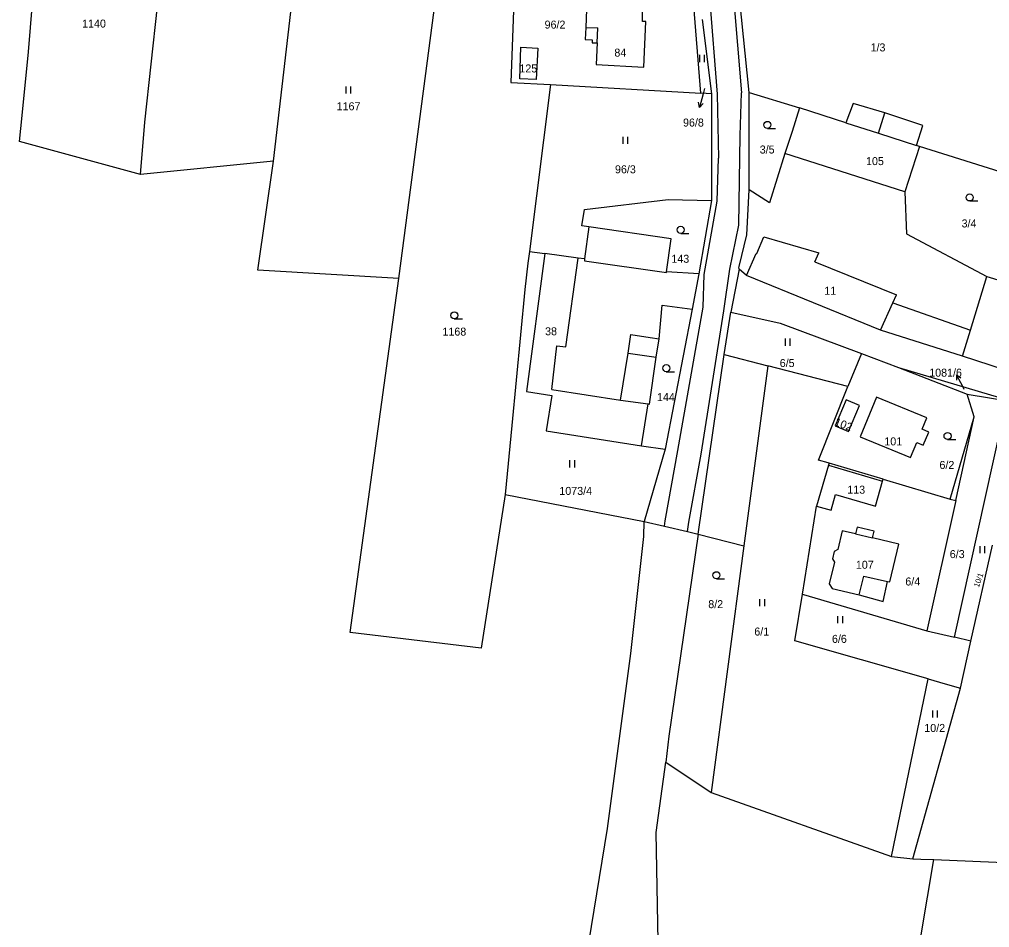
# Model space of a CAD drawing. Extents: x -746176 to -739709, y -1128407 to -1124482.
# Drawn here: x -742307.4 to -742101.3, y -1126433.2 to -1126240.2 of the extents above; entities that cross this region are included whole.
import ezdxf

# ---------------------------------------------------------------- set-up
doc = ezdxf.new("R2010")
doc.units = 0
for name, color, linetype in [('Hranice parcel', 7, 'Continuous'), ('Parcelní čísla', 7, 'Continuous'), ('Pop  PČ popisy', 7, 'Continuous'), ('Vnitřní kresba', 7, 'Continuous'), ('Značky kultur', 7, 'Continuous')]:
    doc.layers.add(name, color=color, linetype=linetype)

msp = doc.modelspace()

# ---------------------------------------------------------------- linework, layer by layer
at = {"layer": 'Hranice parcel'}
for p, q in [((-742152.42, -1126255.73), (-742159.24, -1126187.68)), ((-742253.45, -1126270.36), (-742246.8, -1126213.59)), ((-742226.78, -1126295.24), (-742218.41, -1126231.43)), ((-742162.64, -1126255.9), (-742164.34, -1126234.95)), ((-742162.38, -1126240.19), (-742160.39, -1126256.03)), ((-742194.57, -1126254.06), (-742199.05, -1126289.55)), ((-742194.57, -1126254.06), (-742162.64, -1126255.9)), ((-742160.39, -1126256.03), (-742162.64, -1126255.9)), ((-742160.39, -1126256.03), (-742160.39, -1126278.66)), ((-742152.42, -1126255.73), (-742141.7, -1126259.03)), ((-742152.35, -1126276.44), (-742152.42, -1126255.73)), ((-742116.22, -1126267.19), (-742119.31, -1126276.84)), ((-742090.65, -1126275.25), (-742116.22, -1126267.19)), ((-742253.45, -1126270.36), (-742281.72, -1126273.18)), ((-742119.31, -1126276.84), (-742144.79, -1126268.68)), ((-742160.39, -1126278.66), (-742163.05, -1126294.31)), ((-742199.05, -1126289.55), (-742195.79, -1126289.99)), ((-742163.05, -1126294.31), (-742164.48, -1126301.76)), ((-742154.48, -1126293.27), (-742156.3, -1126302.44)), ((-742164.48, -1126301.76), (-742170.24, -1126331.56)), ((-742157.68, -1126311.4), (-742156.3, -1126302.44)), ((-742163.24, -1126349.58), (-742157.68, -1126311.4)), ((-742157.68, -1126311.4), (-742148.42, -1126313.8)), ((-742128.49, -1126311.19), (-742131.46, -1126318.2)), ((-742128.49, -1126311.19), (-742120.66, -1126314.22)), ((-742131.46, -1126318.2), (-742148.42, -1126313.8)), ((-742120.66, -1126314.22), (-742106.07, -1126319.87)), ((-742120.66, -1126314.22), (-742095.86, -1126321.55)), ((-742137.67, -1126333.86), (-742131.46, -1126318.2)), ((-742106.07, -1126319.87), (-742095.86, -1126321.55)), ((-742175.26, -1126330.82), (-742170.24, -1126331.56)), ((-742170.24, -1126331.56), (-742174.68, -1126346.91)), ((-742135.58, -1126334.46), (-742137.67, -1126333.86)), ((-742135.39, -1126334.52), (-742135.58, -1126334.46)), ((-742123.93, -1126337.94), (-742135.39, -1126334.52)), ((-742204.22, -1126341.19), (-742174.68, -1126346.91)), ((-742108.51, -1126342.48), (-742114.63, -1126370.19)), ((-742141.07, -1126362.36), (-742138.05, -1126343.65)), ((-742105.28, -1126372.36), (-742100.72, -1126351.93)), ((-742141.07, -1126362.36), (-742140.82, -1126362.44)), ((-742140.82, -1126362.44), (-742114.63, -1126370.19)), ((-742114.63, -1126370.19), (-742108.8, -1126371.54)), ((-742105.28, -1126372.36), (-742108.8, -1126371.54)), ((-742107.51, -1126382.37), (-742105.28, -1126372.36)), ((-742122.15, -1126418.14), (-742114.39, -1126380.39)), ((-742114.39, -1126380.39), (-742110.73, -1126381.44)), ((-742110.73, -1126381.44), (-742107.51, -1126382.37)), ((-742117.61, -1126418.59), (-742107.51, -1126382.37)), ((-742170.12, -1126398.06), (-742160.44, -1126404.55)), ((-742160.44, -1126404.55), (-742122.15, -1126418.14)), ((-742122.15, -1126418.14), (-742117.61, -1126418.59)), ((-742113.18, -1126418.78), (-742091.83, -1126419.68))]:
    msp.add_line(p, q, dxfattribs=at)
for points in [[(-742281.72, -1126273.18), (-742307.41, -1126266.17), (-742306.81, -1126260.62), (-742305.51, -1126247.12), (-742302.59, -1126211.7)], [(-742281.72, -1126273.18), (-742280.8, -1126262.02), (-742276.72, -1126225.02), (-742275.09, -1126215.95)], [(-742202.22, -1126232.53), (-742203.02, -1126253.58), (-742194.57, -1126254.06)], [(-742185.73, -1126244.55), (-742185.76, -1126245.16), (-742184.7, -1126245.2), (-742184.9, -1126249.82), (-742174.78, -1126250.38), (-742174.35, -1126240.63), (-742175.05, -1126240.62), (-742175.01, -1126238.6), (-742186.93, -1126238.09), (-742187.1, -1126241.89), (-742187.21, -1126244.49), (-742185.73, -1126244.55)], [(-742200.86, -1126246.11), (-742197.3, -1126246.29), (-742197.64, -1126252.97), (-742201.12, -1126252.84), (-742200.86, -1126246.11)], [(-742116.22, -1126267.19), (-742116.82, -1126267), (-742115.46, -1126262.77), (-742123.54, -1126260.09), (-742130.31, -1126258.08), (-742131.85, -1126262.18), (-742141.7, -1126259.03)], [(-742141.7, -1126259.03), (-742143.26, -1126264), (-742144.79, -1126268.68)], [(-742226.78, -1126295.24), (-742256.74, -1126293.53), (-742253.45, -1126270.36)], [(-742144.79, -1126268.68), (-742148.06, -1126279.2), (-742152.35, -1126276.44)], [(-742154.48, -1126293.27), (-742154.57, -1126293.04), (-742154.53, -1126292.75), (-742152.88, -1126286), (-742152.35, -1126276.44)], [(-742186.42, -1126284.28), (-742187.9, -1126284.06), (-742187.39, -1126280.61), (-742169.61, -1126278.45), (-742160.39, -1126278.66)], [(-742119.31, -1126276.84), (-742118.96, -1126285.81), (-742101.9, -1126294.87), (-742092.74, -1126297.6)], [(-742186.42, -1126284.28), (-742187.38, -1126291.11), (-742188.73, -1126290.93), (-742195.79, -1126289.99)], [(-742163.05, -1126294.31), (-742169.96, -1126293.86), (-742168.98, -1126286.85), (-742186.42, -1126284.28)], [(-742199.05, -1126289.55), (-742199.37, -1126292.03), (-742200.07, -1126297.63), (-742202.82, -1126326.51), (-742204.22, -1126341.19)], [(-742195.79, -1126289.99), (-742199.7, -1126319.29), (-742194.31, -1126320.11), (-742195.53, -1126327.65), (-742175.26, -1126330.82)], [(-742204.22, -1126341.19), (-742209.35, -1126373.83), (-742237.12, -1126370.54), (-742226.78, -1126295.24)], [(-742098.16, -1126314.66), (-742107.1, -1126311.81), (-742124.49, -1126306.28), (-742152.92, -1126294.67), (-742154.48, -1126293.27)], [(-742175.26, -1126330.82), (-742173.87, -1126321.93), (-742173.57, -1126321.97), (-742172.11, -1126311.98), (-742171.53, -1126308.09), (-742170.89, -1126300.93), (-742164.48, -1126301.76)], [(-742156.3, -1126302.44), (-742145.81, -1126304.8), (-742128.49, -1126311.19)], [(-742148.42, -1126313.8), (-742153.49, -1126352.12), (-742160.44, -1126404.55)], [(-742108.51, -1126342.48), (-742104.56, -1126324.65), (-742106.07, -1126319.87)], [(-742131.3, -1126327.79), (-742128.95, -1126322.27), (-742131.75, -1126321.08), (-742134.1, -1126326.6), (-742131.3, -1126327.79)], [(-742116.8, -1126330.16), (-742115.42, -1126330.73), (-742114.25, -1126327.9), (-742115.63, -1126327.32), (-742114.63, -1126324.9), (-742125.3, -1126320.48), (-742128.78, -1126328.9), (-742118.11, -1126333.31), (-742116.8, -1126330.16)], [(-742108.8, -1126371.54), (-742098.88, -1126326.64), (-742097.02, -1126326.92)], [(-742135.39, -1126334.52), (-742135.51, -1126334.93), (-742138.05, -1126343.65)], [(-742138.05, -1126343.65), (-742134.99, -1126344.48), (-742134.01, -1126341.18), (-742125.58, -1126343.66), (-742124.04, -1126338.33), (-742123.93, -1126337.94)], [(-742123.93, -1126337.94), (-742109.71, -1126342.16), (-742108.51, -1126342.48)], [(-742187.6, -1126443.43), (-742182.48, -1126412.17), (-742177.55, -1126374.98), (-742174.74, -1126350.1), (-742174.68, -1126346.91)], [(-742174.68, -1126346.91), (-742170.38, -1126347.91), (-742165.47, -1126349.06), (-742163.24, -1126349.58)], [(-742134.78, -1126361.18), (-742129.01, -1126362.5), (-742123.94, -1126363.89), (-742123.02, -1126359.67), (-742122.51, -1126359.71), (-742120.59, -1126351.76), (-742126.19, -1126350.41), (-742125.85, -1126349), (-742129.47, -1126348.12), (-742129.81, -1126349.53), (-742132.62, -1126348.87), (-742133.58, -1126352.84), (-742134.31, -1126353.29), (-742134.7, -1126354.88), (-742134.27, -1126355.59), (-742135.37, -1126360.18), (-742134.78, -1126361.18)], [(-742163.24, -1126349.58), (-742169.48, -1126392.54), (-742170.12, -1126398.06)], [(-742114.39, -1126380.39), (-742142.67, -1126372.26), (-742141.07, -1126362.36)], [(-742133.47, -1126503.52), (-742138.17, -1126495.9), (-742152.98, -1126479.01), (-742161.38, -1126468.51), (-742167.25, -1126457.12), (-742171.72, -1126436.22), (-742172.13, -1126413.04), (-742170.12, -1126398.06)], [(-742130.78, -1126507.86), (-742119.81, -1126458.38), (-742113.18, -1126418.78)], [(-742117.61, -1126418.59), (-742115.93, -1126418.66), (-742113.18, -1126418.78)]]:
    msp.add_lwpolyline(points, dxfattribs=at)
at = {"layer": 'Pop  PČ popisy'}
for p, q in [((-742162.16, -1126256.02), (-742162.94, -1126258.92)), ((-742161.85, -1126254.86), (-742162.16, -1126256.02)), ((-742162.94, -1126258.92), (-742163.16, -1126257.82)), ((-742162.94, -1126258.92), (-742162.19, -1126258.08)), ((-742106.94, -1126318.4), (-742108.35, -1126315.75)), ((-742108.35, -1126315.75), (-742107.44, -1126316.4)), ((-742108.35, -1126315.75), (-742108.32, -1126316.87)), ((-742106.68, -1126318.88), (-742106.94, -1126318.4))]:
    msp.add_line(p, q, dxfattribs=at)
at = {"layer": 'Vnitřní kresba'}
for p, q in [((-742156.14, -1126230.96), (-742154, -1126255.84)), ((-742160.86, -1126234.67), (-742159.19, -1126256.08)), ((-742187.1, -1126241.89), (-742184.56, -1126242)), ((-742184.7, -1126245.2), (-742184.56, -1126242)), ((-742159.19, -1126256.08), (-742158.88, -1126269.7)), ((-742154.3, -1126264.85), (-742154, -1126255.84)), ((-742124.92, -1126264.4), (-742123.54, -1126260.09)), ((-742131.85, -1126262.18), (-742124.92, -1126264.4)), ((-742154.56, -1126283.96), (-742154.3, -1126264.85)), ((-742124.92, -1126264.4), (-742116.82, -1126267)), ((-742159.2, -1126278.85), (-742158.88, -1126269.7)), ((-742161.92, -1126294.39), (-742159.2, -1126278.85)), ((-742156.48, -1126293.32), (-742154.56, -1126283.96)), ((-742150.78, -1126289.99), (-742149.27, -1126286.44)), ((-742149.27, -1126286.44), (-742137.57, -1126289.85)), ((-742191.36, -1126309.81), (-742188.73, -1126290.93)), ((-742187.38, -1126291.11), (-742187.36, -1126291.53)), ((-742152.92, -1126294.67), (-742150.91, -1126289.93)), ((-742150.91, -1126289.93), (-742150.78, -1126289.99)), ((-742138.41, -1126291.71), (-742137.57, -1126289.85)), ((-742187.36, -1126291.53), (-742169.98, -1126294)), ((-742138.41, -1126291.71), (-742121.1, -1126298.77)), ((-742169.98, -1126294), (-742169.96, -1126293.86)), ((-742162.18, -1126301.35), (-742161.92, -1126294.39)), ((-742157.74, -1126302.18), (-742156.48, -1126293.32)), ((-742105.39, -1126306.24), (-742101.9, -1126294.87)), ((-742121.85, -1126300.43), (-742121.1, -1126298.77)), ((-742167.55, -1126331.85), (-742162.18, -1126301.35)), ((-742124.49, -1126306.28), (-742121.85, -1126300.43)), ((-742121.85, -1126300.43), (-742105.39, -1126306.24)), ((-742162.6, -1126332.62), (-742157.74, -1126302.18)), ((-742178.07, -1126311.14), (-742177.5, -1126307.2)), ((-742177.5, -1126307.2), (-742173.42, -1126307.81)), ((-742107.1, -1126311.81), (-742105.39, -1126306.24)), ((-742194.3, -1126318.85), (-742193.22, -1126309.55)), ((-742193.22, -1126309.55), (-742191.36, -1126309.81)), ((-742173.42, -1126307.81), (-742171.53, -1126308.09)), ((-742179.7, -1126321.11), (-742178.07, -1126311.14)), ((-742178.07, -1126311.14), (-742172.11, -1126311.98)), ((-742194.3, -1126318.85), (-742179.7, -1126321.11)), ((-742179.7, -1126321.11), (-742173.87, -1126321.93)), ((-742109.71, -1126342.16), (-742104.56, -1126324.65)), ((-742170.22, -1126346.76), (-742167.55, -1126331.85)), ((-742165.18, -1126347.04), (-742162.6, -1126332.62)), ((-742135.51, -1126334.93), (-742124.04, -1126338.33)), ((-742170.38, -1126347.91), (-742170.22, -1126346.76)), ((-742165.47, -1126349.06), (-742165.18, -1126347.04)), ((-742163.24, -1126349.58), (-742153.49, -1126352.12)), ((-742129.81, -1126349.53), (-742126.19, -1126350.41)), ((-742129.01, -1126362.5), (-742128.01, -1126358.52)), ((-742128.01, -1126358.52), (-742123.02, -1126359.67))]:
    msp.add_line(p, q, dxfattribs=at)
at = {"layer": 'Značky kultur'}
for p, q in [((-742162.84, -1126249.27), (-742162.84, -1126247.77)), ((-742161.84, -1126249.27), (-742161.84, -1126247.77)), ((-742238.02, -1126255.97), (-742238.02, -1126254.47)), ((-742237.02, -1126255.97), (-742237.02, -1126254.47)), ((-742148.51, -1126263.38), (-742146.76, -1126263.38)), ((-742179.16, -1126266.66), (-742179.16, -1126265.16)), ((-742178.16, -1126266.66), (-742178.16, -1126265.16)), ((-742105.54, -1126278.8), (-742103.79, -1126278.8)), ((-742166.93, -1126285.68), (-742165.18, -1126285.68)), ((-742215.02, -1126303.86), (-742213.27, -1126303.86)), ((-742144.69, -1126309.55), (-742144.69, -1126308.05)), ((-742143.69, -1126309.55), (-742143.69, -1126308.05)), ((-742169.99, -1126315.08), (-742168.24, -1126315.08)), ((-742110.24, -1126329.5), (-742108.49, -1126329.5)), ((-742190.45, -1126335.41), (-742190.45, -1126333.91)), ((-742189.45, -1126335.41), (-742189.45, -1126333.91)), ((-742103.34, -1126353.64), (-742103.34, -1126352.14)), ((-742102.34, -1126353.64), (-742102.34, -1126352.14)), ((-742159.35, -1126359.09), (-742157.6, -1126359.09)), ((-742150.09, -1126364.91), (-742150.09, -1126363.41)), ((-742149.09, -1126364.91), (-742149.09, -1126363.41)), ((-742133.52, -1126368.52), (-742133.52, -1126367.02)), ((-742132.52, -1126368.52), (-742132.52, -1126367.02)), ((-742113.39, -1126388.6), (-742113.39, -1126387.1)), ((-742112.39, -1126388.6), (-742112.39, -1126387.1))]:
    msp.add_line(p, q, dxfattribs=at)
for centre in [(-742148.51, -1126262.63), (-742105.54, -1126278.05), (-742166.93, -1126284.93), (-742215.02, -1126303.11), (-742169.99, -1126314.33), (-742110.24, -1126328.75), (-742159.35, -1126358.34)]:
    msp.add_circle(centre, 0.75, dxfattribs=at)

# ---------------------------------------------------------------- texts
at = {"layer": 'Parcelní čísla'}
for s, p in [('1140', (-742294.09, -1126241.94)), ('96/2', (-742195.84, -1126242.16)), ('1/3', (-742126.6, -1126247.01)), ('84', (-742181.02, -1126248.11)), ('125', (-742201.2, -1126251.48)), ('1167', (-742240.02, -1126259.52)), ('96/8', (-742166.44, -1126262.98)), ('3/5', (-742150.14, -1126268.71)), ('105', (-742127.56, -1126271.17)), ('96/3', (-742180.89, -1126272.91)), ('3/4', (-742107.26, -1126284.42)), ('143', (-742168.91, -1126291.93)), ('11', (-742136.42, -1126298.72)), ('1168', (-742217.54, -1126307.41)), ('38', (-742195.74, -1126307.34)), ('6/5', (-742145.89, -1126314.09)), ('1081/6', (-742114.14, -1126316.14)), ('144', (-742171.97, -1126321.33)), ('101', (-742123.67, -1126330.74)), ('6/2', (-742111.96, -1126335.75)), ('1073/4', (-742192.71, -1126341.27)), ('113', (-742131.54, -1126341.01)), ('6/3', (-742109.77, -1126354.7)), ('107', (-742129.72, -1126356.97)), ('6/4', (-742119.21, -1126360.52)), ('8/2', (-742161.07, -1126365.34)), ('6/1', (-742151.29, -1126371.16)), ('6/6', (-742134.8, -1126372.72)), ('10/2', (-742115.18, -1126391.65))]:
    msp.add_text(s, height=1.7, dxfattribs=at).set_placement(p)
for s, height, rotation, p in [('102', 1.7, 339, (-742134.41, -1126326.41)), ('10/1', 1.19, 71, (-742103.59, -1126361.02))]:
    msp.add_text(s, height=height, rotation=rotation, dxfattribs=at).set_placement(p)

doc.saveas('drawing.dxf')
